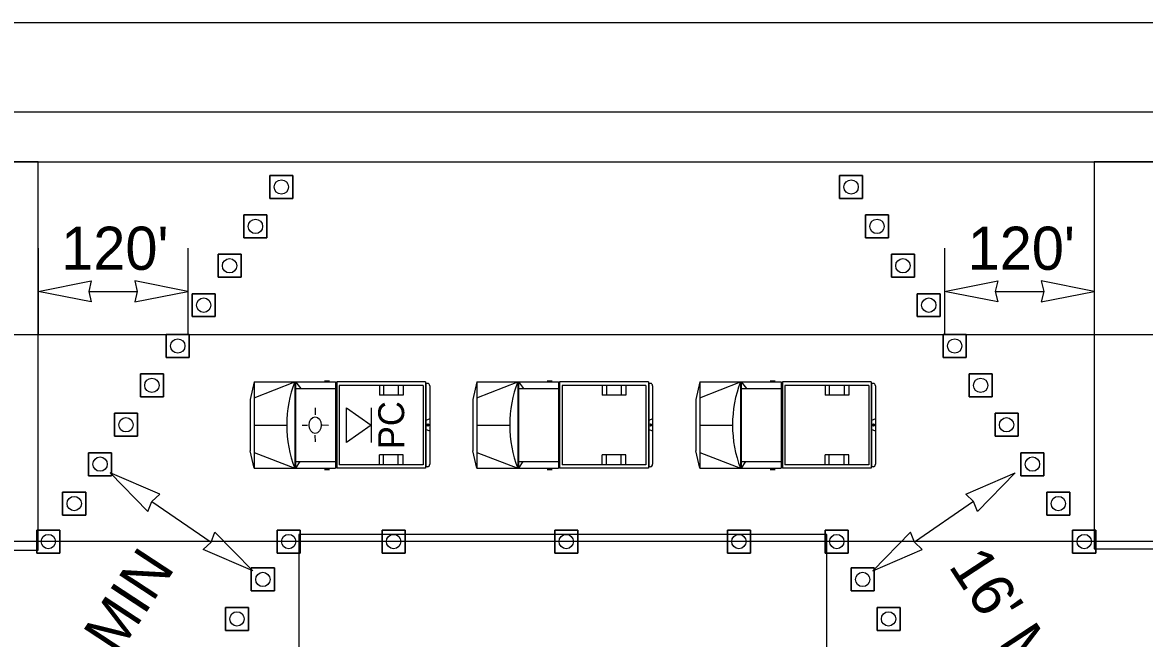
# Model space of a CAD drawing. Extents: x 99999.1 to 100095.7, y 99995 to 100010.7.
# Drawn here: x 100006.052 to 100008.131, y 100004.589 to 100005.732 of the extents above; entities that cross this region are included whole.
import ezdxf

# ---------------------------------------------------------------- set-up
doc = ezdxf.new("R2010")
doc.units = 0
for name, color, linetype in [('RD_ED_ShoulderPavedEdge', 7, 'Continuous'), ('RD_MK_LineEdgeWhite', 7, 'Continuous'), ('RD_MK_LineSkipCenter', 7, 'Continuous'), ('SH_TI_Tables', 7, 'Continuous'), ('TR_WZ_MotoristVehicle', 7, 'Continuous'), ('TR_WZ_PortableSignMountBlk-Wht', 7, 'Continuous'), ('TR_WZ_TrafficCone', 7, 'Continuous'), ('TR_WZ_WorkZoneDetails', 7, 'Continuous'), ('TR_WZ_WorkZoneTextCurrent', 7, 'Continuous')]:
    doc.layers.add(name, color=color, linetype=linetype)

msp = doc.modelspace()

# ---------------------------------------------------------------- linework, layer by layer
at = {"layer": 'RD_ED_ShoulderPavedEdge'}
for p, q in [((100000.1076, 100005.7323), (100015.6424, 100005.7323)), ((100005.1009, 100005.4735), (100009.0183, 100005.4735))]:
    msp.add_line(p, q, dxfattribs=at)
at = {"layer": 'RD_MK_LineEdgeWhite'}
msp.add_line((100005.1009, 100005.1535), (100009.0183, 100005.1535), dxfattribs=at)
at = {"layer": 'RD_MK_LineSkipCenter'}
msp.add_lwpolyline([(100009.0017, 100004.7695), (100005.0844, 100004.7695)], dxfattribs=at)
at = {"layer": 'SH_TI_Tables'}
msp.add_lwpolyline([(100004.9869, 100005.5662), (100009.1323, 100005.5662), (100009.1323, 100003.4755), (100004.9869, 100003.4755)], close=True, dxfattribs=at)
at = {"layer": 'TR_WZ_MotoristVehicle'}
for p, q in [((100006.481, 100005.0655), (100006.4736, 100005.0332)), ((100006.481, 100005.0655), (100006.481, 100004.9055)), ((100006.481, 100005.0655), (100006.6321, 100005.0655)), ((100006.481, 100005.0362), (100006.5566, 100005.0655)), ((100006.5566, 100005.0655), (100006.5566, 100004.9055)), ((100006.5579, 100005.0655), (100006.5579, 100004.9055)), ((100006.5579, 100005.0655), (100006.5675, 100005.0531)), ((100006.6115, 100005.0677), (100006.6206, 100005.0677)), ((100006.6321, 100005.0655), (100006.6321, 100004.9055)), ((100006.7989, 100005.0655), (100006.6343, 100005.0655)), ((100006.6343, 100005.0655), (100006.6343, 100004.9055)), ((100006.7942, 100005.0591), (100006.639, 100005.0591)), ((100006.639, 100005.0591), (100006.639, 100004.9119)), ((100006.7132, 100005.0591), (100006.7132, 100005.0407)), ((100006.7211, 100005.0591), (100006.7211, 100005.0407)), ((100006.7483, 100005.0591), (100006.7483, 100005.0407)), ((100006.7571, 100005.0591), (100006.7571, 100005.0407)), ((100006.7942, 100005.0591), (100006.7942, 100004.9119)), ((100006.7989, 100005.0655), (100006.7989, 100004.9055)), ((100006.803, 100005.0629), (100006.7994, 100005.0629)), ((100006.7994, 100005.0629), (100006.7994, 100004.9081)), ((100006.8066, 100005.058), (100006.8066, 100004.913)), ((100006.894, 100005.0655), (100006.8866, 100005.0332)), ((100006.894, 100005.0655), (100006.894, 100004.9055)), ((100006.894, 100005.0655), (100007.0451, 100005.0655)), ((100006.894, 100005.0362), (100006.9696, 100005.0655)), ((100006.9696, 100005.0655), (100006.9696, 100004.9055)), ((100006.9709, 100005.0655), (100006.9709, 100004.9055)), ((100006.9709, 100005.0655), (100006.9806, 100005.0531)), ((100007.0245, 100005.0677), (100007.0336, 100005.0677)), ((100007.0451, 100005.0655), (100007.0451, 100004.9055)), ((100007.2119, 100005.0655), (100007.0473, 100005.0655)), ((100007.0473, 100005.0655), (100007.0473, 100004.9055)), ((100007.2072, 100005.0591), (100007.052, 100005.0591)), ((100007.052, 100005.0591), (100007.052, 100004.9119)), ((100007.1262, 100005.0591), (100007.1262, 100005.0407)), ((100007.1341, 100005.0591), (100007.1341, 100005.0407)), ((100007.1614, 100005.0591), (100007.1614, 100005.0407)), ((100007.1701, 100005.0591), (100007.1701, 100005.0407)), ((100007.2072, 100005.0591), (100007.2072, 100004.9119)), ((100007.2119, 100005.0655), (100007.2119, 100004.9055)), ((100007.216, 100005.0629), (100007.2125, 100005.0629)), ((100007.2125, 100005.0629), (100007.2125, 100004.9081)), ((100007.2196, 100005.058), (100007.2196, 100004.913)), ((100007.307, 100005.0655), (100007.2996, 100005.0332)), ((100007.307, 100005.0655), (100007.307, 100004.9055)), ((100007.307, 100005.0655), (100007.4581, 100005.0655)), ((100007.307, 100005.0362), (100007.3826, 100005.0655)), ((100007.3826, 100005.0655), (100007.3826, 100004.9055)), ((100007.384, 100005.0655), (100007.384, 100004.9055)), ((100007.384, 100005.0655), (100007.3936, 100005.0531)), ((100007.4375, 100005.0677), (100007.4466, 100005.0677)), ((100007.4581, 100005.0655), (100007.4581, 100004.9055)), ((100007.6249, 100005.0655), (100007.4603, 100005.0655)), ((100007.4603, 100005.0655), (100007.4603, 100004.9055)), ((100007.6202, 100005.0591), (100007.465, 100005.0591)), ((100007.465, 100005.0591), (100007.465, 100004.9119)), ((100007.5392, 100005.0591), (100007.5392, 100005.0407)), ((100007.5472, 100005.0591), (100007.5472, 100005.0407)), ((100007.5744, 100005.0591), (100007.5744, 100005.0407)), ((100007.5832, 100005.0591), (100007.5832, 100005.0407)), ((100007.6202, 100005.0591), (100007.6202, 100004.9119)), ((100007.6249, 100005.0655), (100007.6249, 100004.9055)), ((100007.629, 100005.0629), (100007.6255, 100005.0629)), ((100007.6255, 100005.0629), (100007.6255, 100004.9081)), ((100007.6326, 100005.058), (100007.6326, 100004.913)), ((100006.4736, 100005.0332), (100006.4736, 100004.9378)), ((100006.5579, 100005.0531), (100006.6321, 100005.0531)), ((100006.7571, 100005.0407), (100006.7132, 100005.0407)), ((100006.8866, 100005.0332), (100006.8866, 100004.9378)), ((100006.9709, 100005.0531), (100007.0451, 100005.0531)), ((100007.1701, 100005.0407), (100007.1262, 100005.0407)), ((100007.2996, 100005.0332), (100007.2996, 100004.9378)), ((100007.384, 100005.0531), (100007.4581, 100005.0531)), ((100007.5832, 100005.0407), (100007.5392, 100005.0407)), ((100006.5942, 100005.0172), (100006.5942, 100005.0043)), ((100006.8066, 100004.9968), (100006.7994, 100004.9938)), ((100007.2196, 100004.9968), (100007.2125, 100004.9938)), ((100007.6326, 100004.9968), (100007.6255, 100004.9938)), ((100006.481, 100004.9855), (100006.5417, 100004.9855)), ((100006.5701, 100004.9856), (100006.5802, 100004.9856)), ((100006.6055, 100004.9852), (100006.6055, 100004.9852)), ((100006.6189, 100004.9849), (100006.607, 100004.9852)), ((100006.8066, 100004.9742), (100006.7994, 100004.9772)), ((100006.8047, 100004.9855), (100006.8014, 100004.9855)), ((100006.803, 100004.9877), (100006.803, 100004.9832)), ((100006.894, 100004.9855), (100006.9547, 100004.9855)), ((100007.2196, 100004.9742), (100007.2125, 100004.9772)), ((100007.2177, 100004.9855), (100007.2144, 100004.9855)), ((100007.216, 100004.9877), (100007.216, 100004.9832)), ((100007.307, 100004.9855), (100007.3677, 100004.9855)), ((100007.6326, 100004.9742), (100007.6255, 100004.9772)), ((100007.6307, 100004.9855), (100007.6274, 100004.9855)), ((100007.629, 100004.9877), (100007.629, 100004.9832)), ((100006.5948, 100004.9547), (100006.5945, 100004.9668)), ((100006.481, 100004.9055), (100006.4736, 100004.9378)), ((100006.481, 100004.9348), (100006.5566, 100004.9055)), ((100006.7132, 100004.9119), (100006.7132, 100004.9303)), ((100006.7571, 100004.9303), (100006.7132, 100004.9303)), ((100006.7211, 100004.9119), (100006.7211, 100004.9303)), ((100006.7483, 100004.9119), (100006.7483, 100004.9303)), ((100006.7571, 100004.9119), (100006.7571, 100004.9303)), ((100006.894, 100004.9055), (100006.8866, 100004.9378)), ((100006.894, 100004.9348), (100006.9696, 100004.9055)), ((100007.1262, 100004.9119), (100007.1262, 100004.9303)), ((100007.1701, 100004.9303), (100007.1262, 100004.9303)), ((100007.1341, 100004.9119), (100007.1341, 100004.9303)), ((100007.1614, 100004.9119), (100007.1614, 100004.9303)), ((100007.1701, 100004.9119), (100007.1701, 100004.9303)), ((100007.307, 100004.9055), (100007.2996, 100004.9378)), ((100007.307, 100004.9348), (100007.3826, 100004.9055)), ((100007.5392, 100004.9119), (100007.5392, 100004.9303)), ((100007.5832, 100004.9303), (100007.5392, 100004.9303)), ((100007.5472, 100004.9119), (100007.5472, 100004.9303)), ((100007.5744, 100004.9119), (100007.5744, 100004.9303)), ((100007.5832, 100004.9119), (100007.5832, 100004.9303)), ((100006.5579, 100004.9179), (100006.6321, 100004.9179)), ((100006.5659, 100004.9179), (100006.5579, 100004.9055)), ((100006.7942, 100004.9119), (100006.639, 100004.9119)), ((100006.803, 100004.9081), (100006.7994, 100004.9081)), ((100006.9709, 100004.9179), (100007.0451, 100004.9179)), ((100006.9789, 100004.9179), (100006.9709, 100004.9055)), ((100007.2072, 100004.9119), (100007.052, 100004.9119)), ((100007.216, 100004.9081), (100007.2125, 100004.9081)), ((100007.384, 100004.9179), (100007.4581, 100004.9179)), ((100007.3919, 100004.9179), (100007.384, 100004.9055)), ((100007.6202, 100004.9119), (100007.465, 100004.9119)), ((100007.629, 100004.9081), (100007.6255, 100004.9081)), ((100006.481, 100004.9055), (100006.6321, 100004.9055)), ((100006.6115, 100004.9032), (100006.6206, 100004.9032)), ((100006.7989, 100004.9055), (100006.6343, 100004.9055)), ((100006.894, 100004.9055), (100007.0451, 100004.9055)), ((100007.0245, 100004.9032), (100007.0336, 100004.9032)), ((100007.2119, 100004.9055), (100007.0473, 100004.9055)), ((100007.307, 100004.9055), (100007.4581, 100004.9055)), ((100007.4375, 100004.9032), (100007.4466, 100004.9032)), ((100007.6249, 100004.9055), (100007.4603, 100004.9055))]:
    msp.add_line(p, q, dxfattribs=at)
for centre, major_axis, start_param, end_param in [((100006.6645, 100004.9855), (0, -0.1679), 4.215667, 5.208926), ((100006.803, 100005.058), (0, 0.00488), 4.712389, 6.283185), ((100007.0776, 100004.9855), (0, -0.1679), 4.215667, 5.208926), ((100007.216, 100005.058), (0, 0.00488), 4.712389, 6.283185), ((100007.4906, 100004.9855), (0, -0.1679), 4.215667, 5.208926), ((100007.629, 100005.058), (0, 0.00488), 4.712389, 6.283185), ((100006.803, 100004.913), (0, -0.00488), 0, 1.570796), ((100007.216, 100004.913), (0, -0.00488), 0, 1.570796), ((100007.629, 100004.913), (0, -0.00488), 0, 1.570796)]:
    msp.add_ellipse(centre, major_axis=major_axis, ratio=0.73155, start_param=start_param, end_param=end_param, dxfattribs=at)
for centre, major_axis in [((100006.5942, 100004.9855), (0, 0.0154)), ((100006.803, 100004.9855), (0, 0.00225)), ((100007.216, 100004.9855), (0, 0.00225)), ((100007.629, 100004.9855), (0, 0.00225))]:
    msp.add_ellipse(centre, major_axis=major_axis, ratio=0.73155, dxfattribs=at)
at = {"layer": 'TR_WZ_PortableSignMountBlk-Wht'}
msp.add_line((100006.6981, 100005.0174), (100006.6981, 100004.9534), dxfattribs=at)
msp.add_lwpolyline([(100006.6981, 100004.9855), (100006.6521, 100004.9534), (100006.6521, 100005.0174)], close=True, dxfattribs=at)
at = {"layer": 'TR_WZ_TrafficCone'}
for points in [[(100006.5103, 100005.4484), (100006.5529, 100005.4484), (100006.5529, 100005.4058), (100006.5103, 100005.4058), (100006.5103, 100005.4484)], [(100006.5103, 100005.4058), (100006.5529, 100005.4058), (100006.5529, 100005.4484), (100006.5103, 100005.4484), (100006.5103, 100005.4058)], [(100007.5663, 100005.4484), (100007.6089, 100005.4484), (100007.6089, 100005.4058), (100007.5663, 100005.4058), (100007.5663, 100005.4484)], [(100007.5663, 100005.4058), (100007.6089, 100005.4058), (100007.6089, 100005.4484), (100007.5663, 100005.4484), (100007.5663, 100005.4058)], [(100006.4623, 100005.3754), (100006.5049, 100005.3754), (100006.5049, 100005.3327), (100006.4623, 100005.3327), (100006.4623, 100005.3754)], [(100006.4623, 100005.3327), (100006.5049, 100005.3327), (100006.5049, 100005.3754), (100006.4623, 100005.3754), (100006.4623, 100005.3327)], [(100007.6143, 100005.3754), (100007.6569, 100005.3754), (100007.6569, 100005.3327), (100007.6143, 100005.3327), (100007.6143, 100005.3754)], [(100007.6143, 100005.3327), (100007.6569, 100005.3327), (100007.6569, 100005.3754), (100007.6143, 100005.3754), (100007.6143, 100005.3327)], [(100006.4143, 100005.3023), (100006.4569, 100005.3023), (100006.4569, 100005.2596), (100006.4143, 100005.2596), (100006.4143, 100005.3023)], [(100006.4143, 100005.2596), (100006.4569, 100005.2596), (100006.4569, 100005.3023), (100006.4143, 100005.3023), (100006.4143, 100005.2596)], [(100007.6623, 100005.3023), (100007.7049, 100005.3023), (100007.7049, 100005.2596), (100007.6623, 100005.2596), (100007.6623, 100005.3023)], [(100007.6623, 100005.2596), (100007.7049, 100005.2596), (100007.7049, 100005.3023), (100007.6623, 100005.3023), (100007.6623, 100005.2596)], [(100006.3663, 100005.2292), (100006.4089, 100005.2292), (100006.4089, 100005.1866), (100006.3663, 100005.1866), (100006.3663, 100005.2292)], [(100006.3663, 100005.1866), (100006.4089, 100005.1866), (100006.4089, 100005.2292), (100006.3663, 100005.2292), (100006.3663, 100005.1866)], [(100007.7103, 100005.2292), (100007.7529, 100005.2292), (100007.7529, 100005.1866), (100007.7103, 100005.1866), (100007.7103, 100005.2292)], [(100007.7103, 100005.1866), (100007.7529, 100005.1866), (100007.7529, 100005.2292), (100007.7103, 100005.2292), (100007.7103, 100005.1866)], [(100006.3609, 100005.1535), (100006.3182, 100005.1535), (100006.3182, 100005.1108), (100006.3609, 100005.1108), (100006.3609, 100005.1535)], [(100006.3609, 100005.1108), (100006.3182, 100005.1108), (100006.3182, 100005.1535), (100006.3609, 100005.1535), (100006.3609, 100005.1108)], [(100007.7583, 100005.1535), (100007.801, 100005.1535), (100007.801, 100005.1108), (100007.7583, 100005.1108), (100007.7583, 100005.1535)], [(100007.7583, 100005.1108), (100007.801, 100005.1108), (100007.801, 100005.1535), (100007.7583, 100005.1535), (100007.7583, 100005.1108)], [(100006.3129, 100005.0804), (100006.2702, 100005.0804), (100006.2702, 100005.0378), (100006.3129, 100005.0378), (100006.3129, 100005.0804)], [(100006.3129, 100005.0378), (100006.2702, 100005.0378), (100006.2702, 100005.0804), (100006.3129, 100005.0804), (100006.3129, 100005.0378)], [(100007.8063, 100005.0804), (100007.849, 100005.0804), (100007.849, 100005.0378), (100007.8063, 100005.0378), (100007.8063, 100005.0804)], [(100007.8063, 100005.0378), (100007.849, 100005.0378), (100007.849, 100005.0804), (100007.8063, 100005.0804), (100007.8063, 100005.0378)], [(100006.2649, 100005.0074), (100006.2222, 100005.0074), (100006.2222, 100004.9647), (100006.2649, 100004.9647), (100006.2649, 100005.0074)], [(100006.2649, 100004.9647), (100006.2222, 100004.9647), (100006.2222, 100005.0074), (100006.2649, 100005.0074), (100006.2649, 100004.9647)], [(100007.8543, 100005.0074), (100007.897, 100005.0074), (100007.897, 100004.9647), (100007.8543, 100004.9647), (100007.8543, 100005.0074)], [(100007.8543, 100004.9647), (100007.897, 100004.9647), (100007.897, 100005.0074), (100007.8543, 100005.0074), (100007.8543, 100004.9647)], [(100006.2169, 100004.9343), (100006.1742, 100004.9343), (100006.1742, 100004.8916), (100006.2169, 100004.8916), (100006.2169, 100004.9343)], [(100006.2169, 100004.8916), (100006.1742, 100004.8916), (100006.1742, 100004.9343), (100006.2169, 100004.9343), (100006.2169, 100004.8916)], [(100007.9023, 100004.9343), (100007.945, 100004.9343), (100007.945, 100004.8916), (100007.9023, 100004.8916), (100007.9023, 100004.9343)], [(100007.9023, 100004.8916), (100007.945, 100004.8916), (100007.945, 100004.9343), (100007.9023, 100004.9343), (100007.9023, 100004.8916)], [(100006.1689, 100004.8612), (100006.1262, 100004.8612), (100006.1262, 100004.8186), (100006.1689, 100004.8186), (100006.1689, 100004.8612)], [(100006.1689, 100004.8186), (100006.1262, 100004.8186), (100006.1262, 100004.8612), (100006.1689, 100004.8612), (100006.1689, 100004.8186)], [(100007.9503, 100004.8612), (100007.993, 100004.8612), (100007.993, 100004.8186), (100007.9503, 100004.8186), (100007.9503, 100004.8612)], [(100007.9503, 100004.8186), (100007.993, 100004.8186), (100007.993, 100004.8612), (100007.9503, 100004.8612), (100007.9503, 100004.8186)], [(100006.1209, 100004.7908), (100006.0782, 100004.7908), (100006.0782, 100004.7482), (100006.1209, 100004.7482), (100006.1209, 100004.7908)], [(100006.1209, 100004.7482), (100006.0782, 100004.7482), (100006.0782, 100004.7908), (100006.1209, 100004.7908), (100006.1209, 100004.7482)], [(100006.5665, 100004.7908), (100006.5239, 100004.7908), (100006.5239, 100004.7482), (100006.5665, 100004.7482), (100006.5665, 100004.7908)], [(100006.5665, 100004.7482), (100006.5239, 100004.7482), (100006.5239, 100004.7908), (100006.5665, 100004.7908), (100006.5665, 100004.7482)], [(100006.7183, 100004.7908), (100006.7609, 100004.7908), (100006.7609, 100004.7482), (100006.7183, 100004.7482), (100006.7183, 100004.7908)], [(100006.7183, 100004.7482), (100006.7609, 100004.7482), (100006.7609, 100004.7908), (100006.7183, 100004.7908), (100006.7183, 100004.7482)], [(100007.0383, 100004.7908), (100007.0809, 100004.7908), (100007.0809, 100004.7482), (100007.0383, 100004.7482), (100007.0383, 100004.7908)], [(100007.0383, 100004.7482), (100007.0809, 100004.7482), (100007.0809, 100004.7908), (100007.0383, 100004.7908), (100007.0383, 100004.7482)], [(100007.3583, 100004.7908), (100007.4009, 100004.7908), (100007.4009, 100004.7482), (100007.3583, 100004.7482), (100007.3583, 100004.7908)], [(100007.3583, 100004.7482), (100007.4009, 100004.7482), (100007.4009, 100004.7908), (100007.3583, 100004.7908), (100007.3583, 100004.7482)], [(100007.5397, 100004.7908), (100007.5823, 100004.7908), (100007.5823, 100004.7482), (100007.5397, 100004.7482), (100007.5397, 100004.7908)], [(100007.5397, 100004.7482), (100007.5823, 100004.7482), (100007.5823, 100004.7908), (100007.5397, 100004.7908), (100007.5397, 100004.7482)], [(100008.0409, 100004.7908), (100007.9982, 100004.7908), (100007.9982, 100004.7482), (100008.0409, 100004.7482), (100008.0409, 100004.7908)], [(100008.0409, 100004.7482), (100007.9982, 100004.7482), (100007.9982, 100004.7908), (100008.0409, 100004.7908), (100008.0409, 100004.7482)], [(100006.4759, 100004.6778), (100006.5186, 100004.6778), (100006.5186, 100004.7204), (100006.4759, 100004.7204), (100006.4759, 100004.6778)], [(100006.4759, 100004.7204), (100006.5186, 100004.7204), (100006.5186, 100004.6778), (100006.4759, 100004.6778), (100006.4759, 100004.7204)], [(100007.6303, 100004.6778), (100007.5876, 100004.6778), (100007.5876, 100004.7204), (100007.6303, 100004.7204), (100007.6303, 100004.6778)], [(100007.6303, 100004.7204), (100007.5876, 100004.7204), (100007.5876, 100004.6778), (100007.6303, 100004.6778), (100007.6303, 100004.7204)], [(100006.4279, 100004.6047), (100006.4706, 100004.6047), (100006.4706, 100004.6474), (100006.4279, 100004.6474), (100006.4279, 100004.6047)], [(100006.4279, 100004.6474), (100006.4706, 100004.6474), (100006.4706, 100004.6047), (100006.4279, 100004.6047), (100006.4279, 100004.6474)], [(100007.6783, 100004.6047), (100007.6356, 100004.6047), (100007.6356, 100004.6474), (100007.6783, 100004.6474), (100007.6783, 100004.6047)], [(100007.6783, 100004.6474), (100007.6356, 100004.6474), (100007.6356, 100004.6047), (100007.6783, 100004.6047), (100007.6783, 100004.6474)]]:
    msp.add_lwpolyline(points, dxfattribs=at)
for centre in [(100006.5316, 100005.4271), (100007.5876, 100005.4271), (100006.4836, 100005.354), (100007.6356, 100005.354), (100006.4356, 100005.281), (100007.6836, 100005.281), (100006.3876, 100005.2079), (100007.7316, 100005.2079), (100006.3396, 100005.1322), (100007.7796, 100005.1322), (100006.2916, 100005.0591), (100007.8276, 100005.0591), (100006.2436, 100004.986), (100007.8756, 100004.986), (100006.1956, 100004.913), (100007.9236, 100004.913), (100006.1476, 100004.8399), (100007.9716, 100004.8399), (100006.0996, 100004.7695), (100006.5452, 100004.7695), (100006.7396, 100004.7695), (100007.0596, 100004.7695), (100007.3796, 100004.7695), (100007.561, 100004.7695), (100008.0196, 100004.7695), (100006.4973, 100004.6991), (100007.6089, 100004.6991), (100006.4493, 100004.626), (100007.6569, 100004.626)]:
    msp.add_circle(centre, 0.0133, dxfattribs=at)
at = {"layer": 'TR_WZ_WorkZoneDetails'}
for p, q in [((100006.0809, 100005.3135), (100006.0809, 100005.1535)), ((100006.3583, 100005.3135), (100006.3583, 100005.1535)), ((100007.7609, 100005.3135), (100007.7609, 100005.1535)), ((100008.0383, 100005.3135), (100008.0383, 100005.1535)), ((100006.1747, 100005.2335), (100006.2645, 100005.2335)), ((100007.8547, 100005.2335), (100007.9445, 100005.2335)), ((100006.2915, 100004.8438), (100006.4014, 100004.7682)), ((100007.8147, 100004.8438), (100007.7048, 100004.7682))]:
    msp.add_line(p, q, dxfattribs=at)
for points in [[(100005.1649, 100005.4735), (100005.1649, 100004.7535), (100006.0809, 100004.7535), (100006.0809, 100005.4735)], [(100008.0383, 100005.4735), (100008.0383, 100004.7562), (100008.9542, 100004.7562), (100008.9542, 100005.4735)], [(100006.0809, 100005.2335), (100006.1792, 100005.2528), (100006.1747, 100005.2335), (100006.1792, 100005.2142)], [(100006.3583, 100005.2335), (100006.26, 100005.2528), (100006.2645, 100005.2335), (100006.26, 100005.2142)], [(100007.7609, 100005.2335), (100007.8592, 100005.2528), (100007.8547, 100005.2335), (100007.8592, 100005.2142)], [(100008.0383, 100005.2335), (100007.94, 100005.2528), (100007.9445, 100005.2335), (100007.94, 100005.2142)], [(100006.2143, 100004.897), (100006.2843, 100004.8254), (100006.2915, 100004.8438), (100006.3061, 100004.8571)], [(100007.8919, 100004.897), (100007.8219, 100004.8254), (100007.8147, 100004.8438), (100007.8, 100004.8571)], [(100006.4786, 100004.7151), (100006.3867, 100004.7549), (100006.4014, 100004.7682), (100006.4085, 100004.7867)], [(100006.5639, 100004.7828), (100006.5639, 100004.0655), (100007.5423, 100004.0655), (100007.5423, 100004.7828)], [(100007.6276, 100004.7151), (100007.7195, 100004.7549), (100007.7048, 100004.7682), (100007.6977, 100004.7867)]]:
    msp.add_lwpolyline(points, close=True, dxfattribs=at)

# ---------------------------------------------------------------- texts
at = {"layer": 'TR_WZ_MotoristVehicle'}
msp.add_text('PC', height=0.048, rotation=90, dxfattribs=at).set_placement((100006.7592, 100004.9407))
at = {"layer": 'TR_WZ_WorkZoneTextCurrent'}
for s, rotation, p in [("120'", 360, (100006.1235, 100005.2735)), ("120'", 360, (100007.8035, 100005.2735)), ("16' MIN", 56.6977, (100006.1351, 100004.415)), ("16' MIN", 303.3023, (100007.7668, 100004.7241))]:
    msp.add_text(s, height=0.08, rotation=rotation, dxfattribs=at).set_placement(p)

doc.saveas('drawing.dxf')
